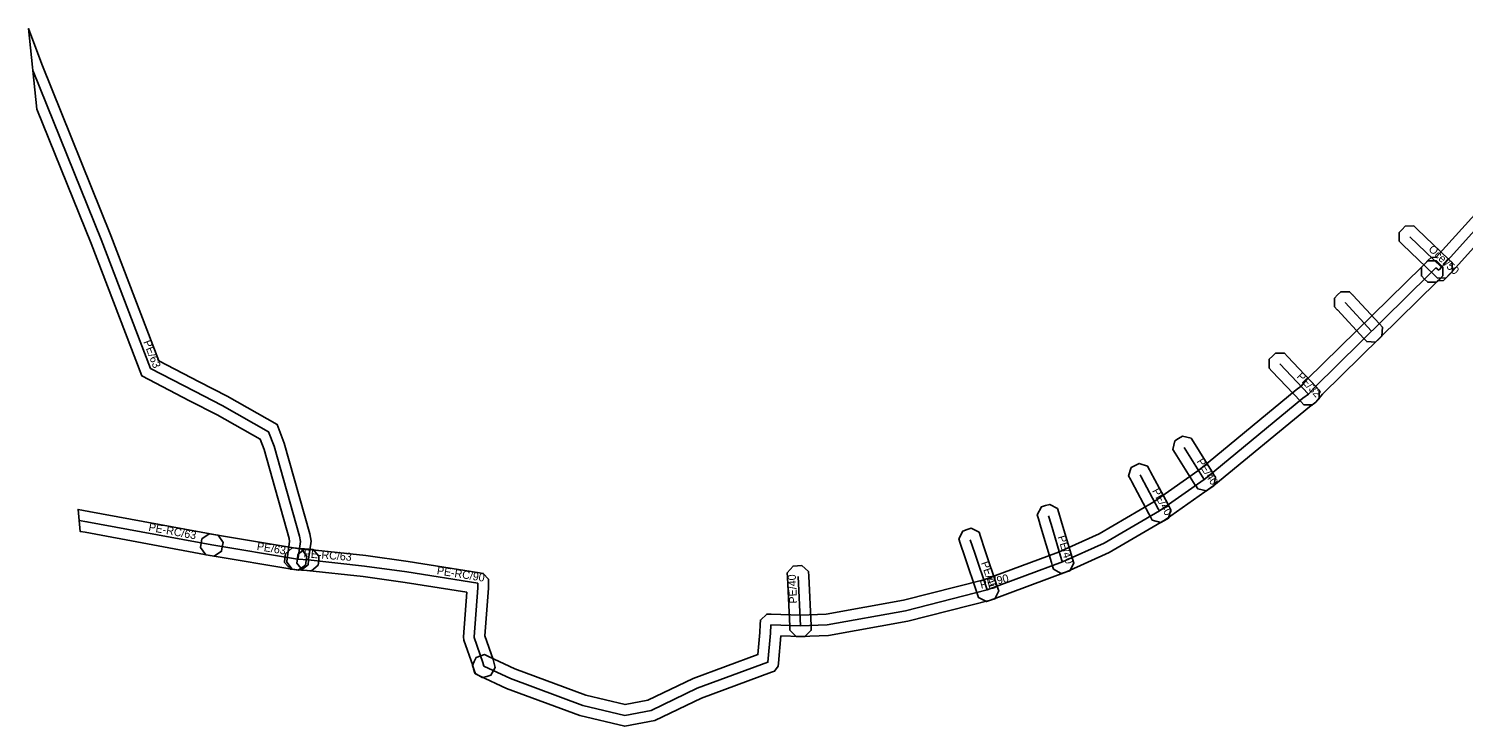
# Model space of a CAD drawing. Extents: x -843502 to -843208, y -997248 to -997028.
# Drawn here: x -843501.6 to -843367.1, y -997241.7 to -997176.3 of the extents above; entities that cross this region are included whole.
import ezdxf

# ---------------------------------------------------------------- set-up
doc = ezdxf.new("R2010")
doc.units = 0
for name, color, linetype in [('1', 7, 'Continuous'), ('24', 7, 'Continuous'), ('25', 7, 'Continuous'), ('30', 7, 'Continuous'), ('51', 7, 'Continuous')]:
    doc.layers.add(name, color=color, linetype=linetype)

msp = doc.modelspace()

# ---------------------------------------------------------------- linework, layer by layer
at = {"layer": '1'}
for points in [[(-843495.7, -997196.45), (-843500.78, -997183.87), (-843501.56, -997176.31), (-843500.33, -997179.65), (-843493.84, -997195.71), (-843489.34, -997207.45), (-843485.56, -997209.42), (-843482.95, -997210.76), (-843478.25, -997213.41), (-843477.59, -997215.16), (-843475.19, -997223.67), (-843475.07, -997224.37), (-843475.31, -997226.05), (-843475.32, -997226.16), (-843475.37, -997226.58), (-843476.02, -997227.09), (-843476.43, -997227.04), (-843476.84, -997226.99), (-843477.36, -997226.34), (-843477.31, -997225.93), (-843477.29, -997225.79), (-843477.09, -997224.41), (-843477.15, -997224.11), (-843479.49, -997215.78), (-843479.87, -997214.79), (-843483.89, -997212.52), (-843486.48, -997211.2), (-843490.94, -997208.87)], [(-843371.69, -997194.81), (-843371.39, -997195.1), (-843368.41, -997197.96), (-843368.11, -997198.25), (-843368.09, -997199.07), (-843368.38, -997199.37), (-843368.67, -997199.67), (-843369.49, -997199.69), (-843369.79, -997199.4), (-843372.77, -997196.54), (-843373.07, -997196.25), (-843373.09, -997195.43), (-843372.8, -997195.13), (-843372.51, -997194.83)], [(-843429.19, -997233.31), (-843431.03, -997233.24), (-843431.25, -997235.8), (-843431.28, -997236.09), (-843431.63, -997236.55), (-843431.91, -997236.65), (-843438.49, -997239.07), (-843442.87, -997241.19), (-843445.68, -997241.72), (-843449.89, -997240.72), (-843456.77, -997238.17), (-843459.3, -997236.99), (-843459.68, -997236.81), (-843459.96, -997236.03), (-843459.79, -997235.66), (-843459.61, -997235.28), (-843458.83, -997235), (-843458.46, -997235.17), (-843455.99, -997236.33), (-843449.31, -997238.8), (-843445.64, -997239.68), (-843443.51, -997239.27), (-843439.27, -997237.23), (-843433.19, -997234.99), (-843433.01, -997232.94), (-843432.98, -997232.17), (-843432.96, -997231.76), (-843432.36, -997231.2), (-843431.94, -997231.21), (-843429.19, -997231.31), (-843426.81, -997231.2), (-843419.56, -997229.91), (-843412, -997227.98), (-843405.03, -997225.38), (-843401.19, -997223.66), (-843396.09, -997220.69), (-843391.95, -997217.77), (-843391.71, -997217.58), (-843382.73, -997210.18), (-843382.26, -997209.84), (-843381.73, -997209.22), (-843370.92, -997198.61), (-843370.7, -997198.38), (-843370.4, -997198.09), (-843369.58, -997198.09), (-843369.28, -997198.38), (-843368.99, -997198.68), (-843368.99, -997199.5), (-843369.28, -997199.8), (-843369.52, -997200.03), (-843380.27, -997210.59), (-843380.9, -997211.32), (-843381.49, -997211.76), (-843390.46, -997219.14), (-843390.76, -997219.37), (-843395.01, -997222.37), (-843400.27, -997225.44), (-843404.27, -997227.24), (-843411.4, -997229.9), (-843419.14, -997231.87), (-843426.59, -997233.2)], [(-843383.83, -997206.75), (-843383.54, -997207.05), (-843380.85, -997209.89), (-843380.57, -997210.19), (-843380.59, -997211.02), (-843380.89, -997211.31), (-843381.19, -997211.59), (-843382.02, -997211.57), (-843382.31, -997211.27), (-843385, -997208.43), (-843385.28, -997208.13), (-843385.26, -997207.3), (-843384.96, -997207.01), (-843384.66, -997206.73)], [(-843390.52, -997218.02), (-843390.51, -997218.03), (-843390.51, -997218.04), (-843390.29, -997218.36), (-843390.45, -997219.17), (-843390.8, -997219.4), (-843391.14, -997219.63), (-843391.95, -997219.47), (-843392.18, -997219.12), (-843392.19, -997219.11), (-843394.07, -997216.12), (-843394.29, -997215.77), (-843394.1, -997214.96), (-843393.75, -997214.74), (-843393.4, -997214.52), (-843392.59, -997214.71), (-843392.37, -997215.06), (-843390.52, -997218.01)], [(-843396.23, -997222.38), (-843396.43, -997222.01), (-843396.54, -997221.81), (-843398.15, -997218.79), (-843398.24, -997218.62), (-843398.44, -997218.25), (-843398.19, -997217.46), (-843397.83, -997217.27), (-843397.46, -997217.07), (-843396.67, -997217.32), (-843396.48, -997217.68), (-843396.39, -997217.85), (-843394.78, -997220.85), (-843394.67, -997221.05), (-843394.47, -997221.41), (-843394.71, -997222.21), (-843395.07, -997222.41), (-843395.43, -997222.61)], [(-843405.49, -997227), (-843405.61, -997226.6), (-843405.68, -997226.37), (-843406.67, -997223.05), (-843406.9, -997222.28), (-843407.02, -997221.88), (-843406.62, -997221.15), (-843406.23, -997221.03), (-843405.83, -997220.91), (-843405.1, -997221.31), (-843404.98, -997221.7), (-843404.75, -997222.47), (-843403.76, -997225.79), (-843403.69, -997226.02), (-843403.57, -997226.42), (-843403.96, -997227.15), (-843404.36, -997227.27), (-843404.76, -997227.39)], [(-843496.27, -997223.53), (-843496.72, -997223.46), (-843496.93, -997221.39), (-843495.91, -997221.57), (-843484.21, -997223.74), (-843483.8, -997223.81), (-843483.33, -997224.49), (-843483.41, -997224.9), (-843483.48, -997225.31), (-843484.17, -997225.78), (-843484.57, -997225.7)], [(-843484.63, -997223.67), (-843484.23, -997223.73), (-843476.37, -997225.04), (-843475.96, -997225.11), (-843475.48, -997225.79), (-843475.54, -997226.19), (-843475.61, -997226.6), (-843476.29, -997227.08), (-843476.69, -997227.02), (-843484.55, -997225.71), (-843484.96, -997225.64), (-843485.44, -997224.96), (-843485.38, -997224.56), (-843485.31, -997224.15)], [(-843412.46, -997223.52), (-843412.33, -997223.92), (-843411.91, -997225.18), (-843410.75, -997228.62), (-843410.62, -997229.01), (-843410.99, -997229.76), (-843411.38, -997229.89), (-843411.77, -997230.02), (-843412.52, -997229.65), (-843412.65, -997229.26), (-843413.81, -997225.82), (-843414.23, -997224.54), (-843414.36, -997224.15), (-843413.99, -997223.41), (-843413.59, -997223.28), (-843413.2, -997223.15)], [(-843475.03, -997227.15), (-843475.45, -997227.12), (-843476.39, -997227.04), (-843476.61, -997227.03), (-843477.02, -997226.99), (-843477.56, -997226.36), (-843477.53, -997225.95), (-843477.49, -997225.54), (-843476.86, -997225), (-843476.45, -997225.03), (-843476.24, -997225.05), (-843475.29, -997225.12), (-843474.88, -997225.16), (-843474.34, -997225.78), (-843474.37, -997226.2), (-843474.41, -997226.61)], [(-843460.79, -997233.34), (-843460.49, -997229.16), (-843466.27, -997228.24), (-843470.19, -997227.69), (-843475.48, -997227.11), (-843475.89, -997227.07), (-843476.41, -997226.42), (-843476.36, -997226.01), (-843476.32, -997225.6), (-843475.67, -997225.08), (-843475.26, -997225.13), (-843469.95, -997225.71), (-843465.97, -997226.26), (-843459.3, -997227.32), (-843458.94, -997227.38), (-843458.46, -997227.94), (-843458.46, -997228.31), (-843458.46, -997228.77), (-843458.78, -997233.23), (-843458.01, -997235.45), (-843457.91, -997235.82), (-843457.81, -997236.22), (-843458.22, -997236.94), (-843458.62, -997237.05), (-843459.03, -997237.15), (-843459.74, -997236.74), (-843459.85, -997236.34), (-843459.93, -997236.03), (-843460.76, -997233.63)], [(-843430.19, -997232.72), (-843430.19, -997232.34), (-843430.43, -997227.73), (-843430.45, -997227.32), (-843429.9, -997226.7), (-843429.48, -997226.68), (-843429.07, -997226.66), (-843428.45, -997227.21), (-843428.43, -997227.63), (-843428.19, -997232.28), (-843428.19, -997232.31), (-843428.19, -997232.72), (-843428.78, -997233.31), (-843429.19, -997233.31), (-843429.6, -997233.31)]]:
    msp.add_lwpolyline(points, close=True, dxfattribs=at)
msp.add_lwpolyline([(-843362.1, -997192.41), (-843368.37, -997199.37), (-843368.59, -997199.59), (-843368.66, -997199.66), (-843368.93, -997199.92), (-843369.44, -997199.96), (-843369.58, -997200.09), (-843370.4, -997200.09), (-843370.7, -997199.8), (-843370.99, -997199.5), (-843370.99, -997198.68), (-843370.7, -997198.38), (-843370.35, -997198.03), (-843370.08, -997197.77), (-843369.6, -997197.74), (-843363.59, -997191.07)], dxfattribs=at)
at = {"layer": '24'}
for points in [[(-843369.99, -997199.09), (-843369.64, -997198.74), (-843369.37, -997198.95), (-843369.3, -997198.88), (-843369.1, -997198.68), (-843362.85, -997191.74), (-843358.15, -997186.46), (-843351.27, -997179.13), (-843348.72, -997176.38)], [(-843501.15, -997180.29), (-843494.77, -997196.08), (-843490.14, -997208.16), (-843486.02, -997210.31), (-843483.42, -997211.64), (-843479.06, -997214.1), (-843478.54, -997215.47), (-843476.17, -997223.89), (-843476.08, -997224.39), (-843476.3, -997225.92), (-843476.32, -997226.05)], [(-843372.08, -997195.82), (-843369.1, -997198.68)], [(-843369.99, -997199.09), (-843370.22, -997199.32), (-843381, -997209.91), (-843381.58, -997210.58), (-843382.11, -997210.97), (-843391.08, -997218.36), (-843391.35, -997218.57), (-843395.55, -997221.53), (-843400.73, -997224.55), (-843404.65, -997226.31), (-843411.7, -997228.94), (-843419.35, -997230.89), (-843426.7, -997232.2), (-843429.19, -997232.31), (-843431.98, -997232.21), (-843432.01, -997233), (-843432.25, -997235.71), (-843438.88, -997238.15), (-843443.19, -997240.23), (-843445.66, -997240.7), (-843449.6, -997239.76), (-843456.38, -997237.25), (-843458.88, -997236.08)], [(-843384.27, -997207.74), (-843381.58, -997210.58)], [(-843391.35, -997218.57), (-843391.35, -997218.57), (-843393.22, -997215.59)], [(-843395.55, -997221.53), (-843395.66, -997221.33), (-843397.27, -997218.32), (-843397.36, -997218.15)], [(-843496.83, -997222.42), (-843496.09, -997222.55), (-843484.39, -997224.72)], [(-843404.65, -997226.31), (-843404.72, -997226.08), (-843405.71, -997222.76), (-843405.94, -997221.99)], [(-843484.39, -997224.72), (-843476.53, -997226.03)], [(-843413.28, -997224.23), (-843412.86, -997225.5), (-843411.7, -997228.94)], [(-843475.37, -997226.12), (-843476.32, -997226.05), (-843476.53, -997226.03)], [(-843458.88, -997236.08), (-843458.97, -997235.74), (-843459.78, -997233.41), (-843459.79, -997233.32), (-843459.46, -997228.73), (-843459.46, -997228.31), (-843466.12, -997227.25), (-843470.07, -997226.7), (-843475.37, -997226.12)], [(-843429.19, -997232.31), (-843429.19, -997232.31), (-843429.43, -997227.68)]]:
    msp.add_lwpolyline(points, dxfattribs=at)
at = {"layer": '25'}
msp.add_lwpolyline([(-843375.67, -997204.67), (-843378.14, -997201.98), (-843378.14, -997201.98)], dxfattribs=at)
at = {"layer": '51'}
msp.add_lwpolyline([(-843376.4, -997205.35), (-843378.86, -997202.68), (-843378.88, -997202.66), (-843379.14, -997202.4), (-843379.14, -997201.57), (-843378.85, -997201.28), (-843378.56, -997200.98), (-843377.73, -997200.98), (-843377.44, -997201.28), (-843377.42, -997201.29), (-843374.93, -997203.99), (-843374.65, -997204.3), (-843374.69, -997205.13), (-843374.99, -997205.41), (-843375.29, -997205.69), (-843376.12, -997205.65)], close=True, dxfattribs=at)

# ---------------------------------------------------------------- texts
at = {"layer": '30'}
for s, rotation, p in [('Ocel/50', 316.1771, (-843370.39, -997197.05)), ('PE/63', 290.9707, (-843490.82, -997205.67)), ('PE/32', 313.4462, (-843382.73, -997208.96)), ('PE/40', 302.1073, (-843392.09, -997216.88)), ('PE/40', 298.1416, (-843396.26, -997219.64)), ('PE-RC/63', 349.4927, (-843490.36, -997223.38)), ('PE/40', 286.6042, (-843405.1, -997223.95)), ('PE/63', 350.5377, (-843480.21, -997225.18)), ('PE-RC/63', 355.5827, (-843475.8, -997225.87)), ('PE/40', 288.6346, (-843412.29, -997226.39)), ('PE-RC/90', 350.9567, (-843463.33, -997227.46)), ('PE/40', 92.9692, (-843429.51, -997230.19)), ('PE/90', 14.3003, (-843412.27, -997228.83))]:
    msp.add_text(s, height=0.75, rotation=rotation, dxfattribs=at).set_placement(p)

doc.saveas('drawing.dxf')
